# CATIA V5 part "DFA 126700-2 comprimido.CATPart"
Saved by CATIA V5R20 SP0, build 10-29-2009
Part number: DFA 126700-2 comprimido
Revision: ANY
Definition: UNKNOWN
Nomenclature: DFA 126700-2 comprimido
Source: Unknown
Bounding box of the stored display mesh (mm): x -2.8 to 2.8, y 0 to 5, z -2.8 to 2.8
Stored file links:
  C:\Users\Utente\Desktop\IO LAVORO\3D X SITO CF\CUMSA\3D files FA\FA 126708-21\DFA 126700-2 comprimido.CATPart
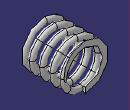
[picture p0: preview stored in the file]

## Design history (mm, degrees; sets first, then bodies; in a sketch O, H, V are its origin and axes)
Body1 "Cortar-Extruir1" (main body)
  Solid1: solid without history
